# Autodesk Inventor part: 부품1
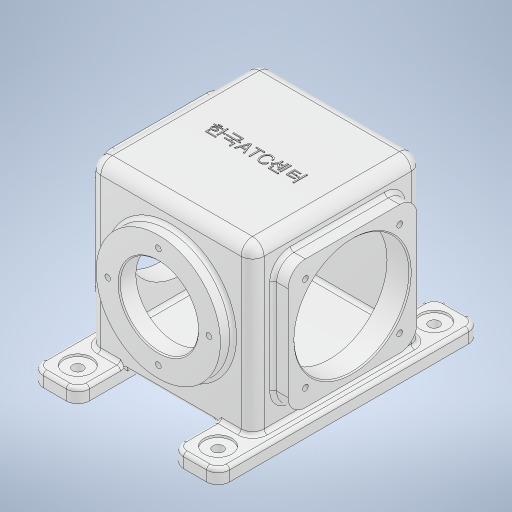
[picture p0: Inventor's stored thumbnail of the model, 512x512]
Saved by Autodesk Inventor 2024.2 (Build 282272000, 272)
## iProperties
Created: 2026-01
Part Number: 부품1
Material: 알루미늄 6061
Document SubType Name: Modeling
Designer: home
Density: 2.7 g/cm^3
Appearance: 알루미늄 - 평지
Mass: 2675.29 g
Surface Area: 2461.71 cm^2
Volume: 990.847 cm^3
Author: home
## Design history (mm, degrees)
sketch "스케치1"
  geometry: L1 (81, -114)-(41, -114); L2 (41, -114)-(41, 114); L3 (41, 114)-(81, 114); L4 (81, 114)-(81, -114); L5 (-41, -114)-(-81, -114); L6 (-81, -114)-(-81, 114); L7 (-81, 114)-(-41, 114); L8 (-41, 114)-(-41, -114); 3 further points
  constraints: 16 end point, 4 parallel, 2 horizontal, 2 horizontal alignment, 2 midpoint, 2 perpendicular
  dimensions: "d0" = 228 distance of L3.end L1.start; "d1" = 228 distance of L5.end L6.end; "d2" = 81 distance from line of point (0, 0) L4; "d3" = 81 distance from line of point (0, 0) L6; "d4" = 40 distance of L1.start L1.end; "d5" = 40 distance of L5.start L5.end
extrude "돌출1" new body sketch "스케치1" distance "d6" = 12; taper "d7" = 0 deg
sketch "스케치2"
  geometry: L1 (-130.405, 82)-(130.405, 82); L2 (-71, 9)-(71, 9); L3 (71, 9)-(71, 155); L4 (71, 155)-(-71, 155); L5 (-71, 155)-(-71, 9); L6 (-71, 9)-(71, 155); L7 (71, 9)-(-71, 155); 2 further points
  constraints: 14 end point, 3 midpoint, 2 horizontal, 2 parallel, 1 perpendicular, 1 vertical alignment
  dimensions: "d8" = 82 distance from line of point (0, 0) L1; "d9" = 142 distance of L3.end L4.end; "d10" = 146 distance of L2.end L3.end
extrude "돌출2" join sketch "스케치2" stored distance "d11" = 148; taper "d12" = 0 deg
sketch "스케치4"
  geometry: L1 (71, 12)-(41, 12) reference; L2 (71, 12)-(71, 155) reference; L3 (71, 155)-(-71, 155) reference; L4 (-71, 155)-(-71, 12) reference; L5 (-41, 12)-(-71, 12) reference; L6 (-41, 9)-(-41, 12) reference; L7 (-41, 9)-(41, 9) reference; L8 (41, 12)-(41, 9) reference; C1 r 54 at (0, 82); 1 further point
  constraints: 1 centre point
  dimensions: "d14" = 108 diameter of C1; "d15" = 82 distance of point (0, 0) C1.centre
extrude "돌출3" join sketch "스케치4" distance "d16" = 11; taper "d17" = 0 deg
sketch "스케치5"
  geometry: L1 (-130, 14)-(-18, 14); L2 (-18, 14)-(-18, 126); L3 (-18, 126)-(-130, 126); L4 (-130, 126)-(-130, 14); L5 (-130, 14)-(-18, 126); L6 (-18, 14)-(-130, 126); L7 (-188, -12)-(40, -12) reference; 4 further points
  constraints: 12 end point, 4 midpoint, 2 parallel, 1 horizontal, 1 perpendicular, 1 vertical alignment
  dimensions: "d18" = 82 distance of point (-74, -12) point (-74, 70); "d19" = 112 distance of L2.end L3.end; "d20" = 112 distance of L1.end L2.end
extrude "돌출4" join sketch "스케치5" distance "d21" = 13; taper "d22" = 0 deg
sketch "스케치6"
  geometry: L1 (71, 155)-(-71, 155) reference; L2 (71, 12)-(41, 12) reference; L3 (71, 12)-(71, 155) reference; L4 (71, 155)-(-71, 155) reference; L5 (-71, 155)-(-71, 12) reference; L6 (-41, 12)-(-71, 12) reference; L7 (-41, 9)-(-41, 12) reference; L8 (-41, 9)-(41, 9) reference; L9 (41, 12)-(41, 9) reference; L10 (-71, 155)-(-71, 12) reference; L11 (-64, 16)-(64, 16); L12 (64, 16)-(64, 148); L13 (64, 148)-(-64, 148); L14 (-64, 148)-(-64, 16); L15 (-64, 16)-(64, 148); L16 (64, 16)-(-64, 148); C1 r 54 at (0, 82) reference; 1 further point
  constraints: 12 end point, 2 midpoint, 2 parallel, 1 horizontal, 1 perpendicular
  dimensions: "d23" = 7 distance between parallel lines of L13 L1; "d24" = 7 distance between parallel lines of L3 L12
extrude "돌출6" cut sketch "스케치6" stored distance "d27" = 141; taper "d28" = 0 deg
sketch "스케치7"
  geometry: L1 (82, 122.894)-(82, -126.18); L2 (136, 85)-(28, 85) reference; L3 (148, 70.5)-(16, 70.5) reference; L4 (82, 85)-(116, 85); L5 (116, 85)-(116, 70.5); L6 (116, 70.5)-(82, 70.5); L7 (82, 70.5)-(82, 85); 4 further points
  constraints: 10 end point, 2 parallel, 1 horizontal, 1 midpoint, 1 perpendicular, 1 point on line, 1 vertical
  dimensions: "d29" = 82 distance from line of point (0, 0) L1; "d30" = 68 diameter of L5 L1
revolve "회전1" sketch "스케치7" stored, may be unused: angle "d31" = 90 deg
node "작업 평면1"
sketch "스케치8"
  geometry: L1 (84, 56)-(84, -56) reference; L2 (64, -70.5)-(64, 70.5) reference; L3 (-64, 70.5)-(-64, -70.5) reference; L4 (-84, 56)-(-84, -56) reference; L5 (133.409, 0)-(-211.285, 0); L6 (84, -1.643)-(64, -1.643); L7 (64, -1.643)-(64, -50); L8 (64, -50)-(84, -50); L9 (84, -50)-(84, -1.643); L10 (-84, 0)-(-64, 0); L11 (-64, 0)-(-64, -50); L12 (-64, -50)-(-84, -50); L13 (-84, -50)-(-84, 0); 7 further points
  constraints: 18 end point, 5 point on line, 4 parallel, 3 horizontal, 2 perpendicular, 1 midpoint
  dimensions: "d33" = 100 diameter of L8 L5; "d34" = 100 diameter of L12 L5
revolve "회전2" sketch "스케치8" stored, may be unused: angle "d35" = 360 deg
fillet "모깎기1" dims "d36" = 10
sketch "스케치9"
  geometry: L1 (-41, -104)-(-41, -74) reference; L2 (-41, -74)-(-71, -74) reference; L3 (-71, -74)-(-71, 74) reference; L4 (-71, 74)-(-41, 74) reference; L5 (-41, 74)-(-41, 104) reference; L6 (-51, 114)-(-71, 114) reference; L7 (-81, 104)-(-81, -104) reference; L8 (-71, -114)-(-51, -114) reference; L9 (-71, -74)-(-71, 74) reference; L10 (71, -74)-(-71, -74) reference; L11 (71, 74)-(71, -74) reference; L12 (-71, 74)-(71, 74) reference; A1 r 10 centre (-51, -104) between (-51, -114) and (-41, -104) reference; A2 r 10 centre (-51, 104) between (-41, 104) and (-51, 114) reference; A3 r 10 centre (-71, 104) between (-71, 114) and (-81, 104) reference; A4 r 10 centre (-71, -104) between (-81, -104) and (-71, -114) reference; 5 further points
  dimensions: "d37" = 94 vertical distance of point (0, 0) point (61, 94); "d38" = 94 vertical distance of point (0, 0) point (61, -94); "d39" = 94 vertical distance of point (0, 0) point (-61, 94); "d40" = 94 vertical distance of point (0, 0) point (-61, -94); "d41" = 61 horizontal distance of point (0, 0) point (-61, -94); "d42" = 61 horizontal distance of point (0, 0) point (61, -94); "d43" = 61 horizontal distance of point (0, 0) point (-61, 94); "d44" = 61 horizontal distance of point (0, 0) point (61, 94)
hole "구멍1" sketch "스케치9" at (-61, 94), (61, 94), (-61, -94), (61, -94) diameter "d45" = 9; stored, may be unused: countersink angle "d49" = 90 deg, drill point angle "d51" = 0 deg; dims "d46" = 16, "d47" = 24, "d48" = 2, "d50" = 18
sketch "스케치10"
  geometry: C1 r 54 at (0, 0) reference; A1 r 44 centre (0, 0) between (0, 44) and (-44, 0); 3 further points
  constraints: 4 point on circle, 1 centre point, 1 coincident
  dimensions: "d52" = 88 diameter of A1
hole "구멍2" sketch "스케치10" at (0, 44), (-44, 0), (0, -44), (44, 0) diameter "d53" = 4.917; stored, may be unused: countersink angle "d57" = 90 deg, drill point angle "d59" = 118 deg; dims "d54" = 12, "d55" = 24, "d56" = 2, "d58" = 14
sketch "스케치11"
  geometry: L1 (-115, 29)-(-33, 29); L2 (-33, 29)-(-33, 111); L3 (-33, 111)-(-115, 111); L4 (-115, 111)-(-115, 29); L5 (-115, 29)-(-33, 111); L6 (-33, 29)-(-115, 111); C1 r 50 at (-74, 70) reference; 5 further points
  constraints: 12 end point, 4 coincident, 2 midpoint, 2 parallel, 1 horizontal, 1 perpendicular
  dimensions: "d60" = 82 distance of L2.end L3.end; "d61" = 82 distance of L1.end L2.end
hole "구멍3" sketch "스케치11" at (-115, 111), (-115, 29), (-33, 29), (-33, 111) diameter "d62" = 4.917; stored, may be unused: countersink angle "d66" = 90 deg, drill point angle "d68" = 118 deg; dims "d63" = 12, "d64" = 4, "d65" = 2, "d67" = 14
fillet "모깎기2" dims "d69" = 10
fillet "모깎기3" dims "d70" = 10
fillet "모깎기4" dims "d71" = 3
fillet "모깎기5" dims "d72" = 3
fillet "모깎기6" dims "d73" = 3
fillet "모깎기7" dims "d74" = 3
chamfer "모따기1" distance "d75" = 1; stored, may be unused: second distance "d76" = 2, angle "d77" = 45 deg
chamfer "모따기2" distance "d78" = 1; stored, may be unused: second distance "d79" = 2, angle "d80" = 45 deg
fillet "모깎기8" dims "d81" = 15
fillet "모깎기9" dims "d82" = 3
fillet "모깎기10" dims "d83" = 15
fillet "모깎기11" dims "d84" = 3
fillet "모깎기12" dims "d85" = 3
sketch "스케치12"
  geometry: L1 (19.521, -57.996)-(102.479, -57.996); L2 (102.479, -57.996)-(102.479, -70.004); L3 (102.479, -70.004)-(19.521, -70.004); L4 (19.521, -70.004)-(19.521, -57.996); 3 further points
  constraints: 2 midpoint, 1 horizontal alignment, 1 vertical alignment, 2 other
feature "엠보싱1" sketch "스케치12" dims "d86" = 0.5, "d87" = 0
fillet "모깎기13" dims "d88" = 3
node "작업 평면2"
node "솔리드1"
mirror "미러1"
mirror "미러2"
node "투영된 루프2"
node "투영된 루프3"
node "투영된 루프4"
node "투영된 루프5"
feature "A9D066F2-1C7D-4E18-AEED-F7BC21143FA4" dims "d45" = 9, "d46" = 16, "d47" = 24, "d48" = 2, "d49" = 90 deg, "d50" = 18, "d51" = 0
other parameters: "d32" = 82, "d89" = 94.25
